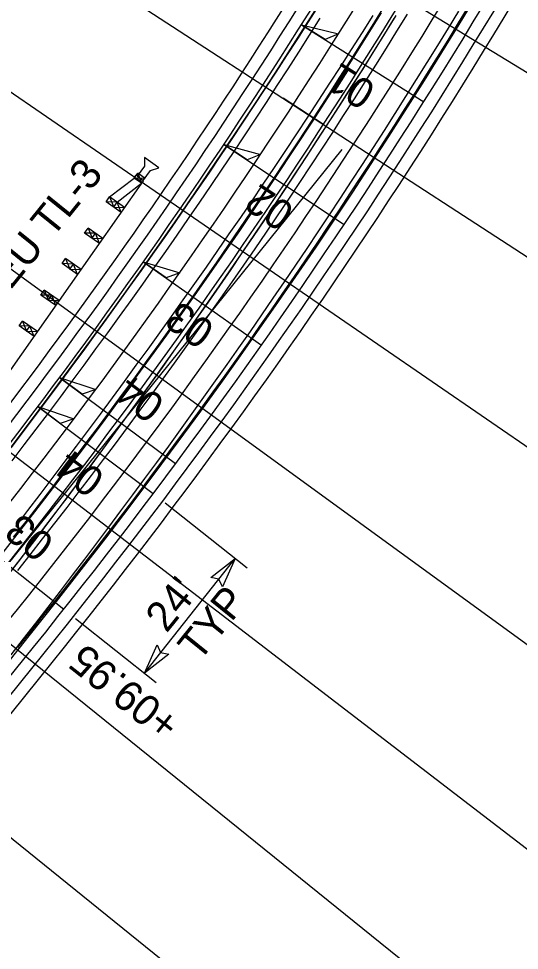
# Model space of a CAD drawing. Extents: x 2293233 to 2294507, y 892788 to 894229.
# Drawn here: x 2294077.1 to 2294160.2, y 893651.6 to 893806.4 of the extents above; entities that cross this region are included whole.
import ezdxf

# ---------------------------------------------------------------- set-up
doc = ezdxf.new("R2010")
doc.units = 0
for name, color, linetype in [('COGO Default Curve', 7, 'Continuous'), ('Prop Dimension', 7, 'Continuous'), ('Prop EOT', 7, 'Continuous'), ('Prop Guardrail Anchor Unit CELL', 7, 'Continuous'), ('Prop Horizontal Alignment', 7, 'Continuous'), ('Prop Paved Shoulder', 7, 'Continuous'), ('Prop Superelevation  Arrow CELL', 7, 'Continuous'), ('Prop Superelevation Label', 7, 'Continuous'), ('Scratch_Level_4', 7, 'Continuous'), ('Scratch_Level_5', 7, 'Continuous'), ('Typical Terminator CELL', 7, 'Continuous')]:
    doc.layers.add(name, color=color, linetype=linetype)

# ---------------------------------------------------------------- blocks, each defined once
blk = doc.blocks.new('TERMINATOR')
at = {"layer": 'Typical Terminator CELL'}
blk.add_lwpolyline([(-0.469, 0.081), (0, 0), (-0.471, -0.083), (-0.411, 0)], close=True, dxfattribs=at)

msp = doc.modelspace()

# ---------------------------------------------------------------- linework, layer by layer
at = {"layer": 'COGO Default Curve'}
for points in [[(2294153.14, 893810.31), (2294150.2, 893805.46), (2294144.41, 893796.11), (2294138.51, 893786.83), (2294132.51, 893777.61), (2294126.4, 893768.47), (2294120.19, 893759.4), (2294113.87, 893750.39), (2294110.57, 893745.78), (2294107.25, 893741.2), (2294103.51, 893736.09), (2294099.53, 893730.74), (2294095.52, 893725.42), (2294091.47, 893720.12), (2294087.39, 893714.85), (2294083.28, 893709.6), (2294078.73, 893703.85), (2294073.94, 893697.86), (2293868.79, 893443.63)], [(2294126.92, 893808.67), (2294125.15, 893805.87), (2294123.36, 893803.07), (2294121.56, 893800.29), (2294119.76, 893797.5), (2294117.95, 893794.73), (2294116.13, 893791.96), (2294114.29, 893789.19), (2294112.45, 893786.43), (2294110.61, 893783.68), (2294108.75, 893780.93), (2294106.88, 893778.19), (2294105, 893775.46), (2294103.12, 893772.73), (2294101.22, 893770.01), (2294099.32, 893767.3), (2294097.41, 893764.59), (2294095.49, 893761.89), (2294093.55, 893759.19), (2294091.61, 893756.5), (2294089.66, 893753.82), (2294087.71, 893751.14), (2294085.74, 893748.47), (2294083.77, 893745.8), (2294081.79, 893743.13), (2294079.8, 893740.47), (2294077.8, 893737.81), (2294075.8, 893735.16)], [(2293934.91, 893558.24), (2293982.19, 893616.89), (2294012.67, 893654.83), (2294024.95, 893670.19), (2294035.75, 893683.75), (2294045.26, 893695.77), (2294053.92, 893706.78), (2294061.7, 893716.77), (2294068.83, 893726.01), (2294075.49, 893734.76), (2294081.7, 893743.02), (2294085.47, 893748.1), (2294089.22, 893753.21), (2294092.74, 893758.07), (2294096.24, 893762.94), (2294099.7, 893767.84), (2294102.95, 893772.49), (2294106.35, 893777.42), (2294109.73, 893782.38), (2294113.08, 893787.36), (2294116.39, 893792.36), (2294119.68, 893797.38), (2294123.12, 893802.7), (2294126.34, 893807.75)], [(2294137.26, 893807.39), (2294131.61, 893798.35), (2294125.85, 893789.36), (2294119.8, 893780.17), (2294113.84, 893771.33), (2294107.78, 893762.55), (2294101.61, 893753.84), (2294095.16, 893744.94), (2294091.39, 893739.84), (2294087.6, 893734.78), (2294083.76, 893729.73), (2294079.69, 893724.45), (2294075.59, 893719.2), (2294071.04, 893713.45), (2294059.17, 893698.61), (2294044.74, 893680.7), (2293954.06, 893568.41)], [(2294075.83, 893700.72), (2294077.88, 893703.35), (2294079.92, 893705.99), (2294081.96, 893708.64), (2294083.99, 893711.29), (2294086.02, 893713.95), (2294088.04, 893716.61), (2294090.05, 893719.28), (2294092.06, 893721.95), (2294094.06, 893724.63), (2294096.05, 893727.31), (2294098.04, 893730), (2294100.01, 893732.69), (2294101.98, 893735.39), (2294103.94, 893738.1), (2294105.9, 893740.81), (2294107.84, 893743.52), (2294109.78, 893746.25), (2294111.71, 893748.98), (2294113.63, 893751.71), (2294115.55, 893754.45), (2294117.45, 893757.2), (2294119.35, 893759.95), (2294121.23, 893762.71), (2294123.11, 893765.48), (2294124.98, 893768.25), (2294126.84, 893771.02), (2294128.69, 893773.81), (2294130.54, 893776.6), (2294132.37, 893779.39), (2294134.19, 893782.19), (2294136.01, 893785), (2294137.81, 893787.81), (2294139.61, 893790.63), (2294141.4, 893793.46), (2294143.17, 893796.29), (2294144.94, 893799.13), (2294146.7, 893801.97), (2294148.45, 893804.82), (2294150.19, 893807.68)], [(2294137.48, 893808.02), (2294135.72, 893805.18), (2294133.94, 893802.34), (2294132.16, 893799.51), (2294130.37, 893796.68), (2294128.56, 893793.86), (2294126.75, 893791.05), (2294124.92, 893788.24), (2294123.09, 893785.44), (2294121.24, 893782.64), (2294119.39, 893779.85), (2294117.53, 893777.07), (2294115.65, 893774.3), (2294113.77, 893771.53), (2294111.88, 893768.77), (2294109.98, 893766.01), (2294108.06, 893763.26), (2294106.14, 893760.52), (2294104.21, 893757.79), (2294102.27, 893755.06), (2294100.32, 893752.34), (2294098.36, 893749.63), (2294096.39, 893746.92), (2294094.41, 893744.22), (2294092.42, 893741.52), (2294090.42, 893738.84), (2294088.41, 893736.16), (2294086.39, 893733.49), (2294084.36, 893730.82), (2294082.33, 893728.17), (2294080.28, 893725.52), (2294078.23, 893722.87), (2294076.16, 893720.24)], [(2294076.9, 893701.92), (2294079, 893704.52), (2294081.09, 893707.13), (2294083.16, 893709.74), (2294085.24, 893712.36), (2294087.3, 893714.99), (2294089.35, 893717.63), (2294091.4, 893720.27), (2294093.43, 893722.92), (2294095.46, 893725.58), (2294097.48, 893728.25), (2294099.48, 893730.93), (2294101.48, 893733.61), (2294103.47, 893736.3), (2294105.46, 893738.99), (2294107.43, 893741.7), (2294109.39, 893744.41), (2294111.34, 893747.12), (2294113.29, 893749.85), (2294115.22, 893752.58), (2294117.15, 893755.31), (2294119.06, 893758.06), (2294120.97, 893760.81), (2294122.86, 893763.57), (2294124.75, 893766.33), (2294126.63, 893769.1), (2294128.49, 893771.88), (2294130.35, 893774.66), (2294132.2, 893777.45), (2294134.04, 893780.25), (2294135.87, 893783.05), (2294137.69, 893785.86), (2294139.49, 893788.68), (2294141.29, 893791.5), (2294143.08, 893794.33), (2294144.86, 893797.17), (2294146.63, 893800.01), (2294148.39, 893802.85), (2294150.14, 893805.71), (2294151.88, 893808.57)], [(2294076.92, 893714.74), (2294078.98, 893717.35), (2294081.04, 893719.97), (2294083.08, 893722.59), (2294085.11, 893725.22), (2294087.13, 893727.86), (2294089.15, 893730.5), (2294091.15, 893733.15), (2294093.14, 893735.8), (2294095.13, 893738.46), (2294097.1, 893741.13), (2294099.07, 893743.81), (2294101.03, 893746.49), (2294102.97, 893749.18), (2294104.91, 893751.88), (2294106.84, 893754.58), (2294108.76, 893757.29), (2294110.67, 893760), (2294112.56, 893762.73), (2294114.45, 893765.45), (2294116.33, 893768.19), (2294118.21, 893770.93), (2294120.07, 893773.68), (2294121.92, 893776.44), (2294123.76, 893779.2), (2294125.59, 893781.96), (2294127.42, 893784.74), (2294129.23, 893787.52), (2294131.03, 893790.3), (2294132.83, 893793.1), (2294134.61, 893795.9), (2294136.38, 893798.7), (2294138.15, 893801.51), (2294139.9, 893804.33), (2294141.65, 893807.15)], [(2293932.89, 893536.61), (2294046.75, 893677.72), (2294053.42, 893686.04), (2294059.44, 893693.61), (2294065.01, 893700.68), (2294070.34, 893707.51), (2294075.44, 893714.1), (2294080.29, 893720.46), (2294085.11, 893726.85), (2294089.69, 893733), (2294096.97, 893742.96), (2294103.95, 893752.72), (2294107.4, 893757.63), (2294110.82, 893762.56), (2294114.21, 893767.5), (2294117.58, 893772.47), (2294120.92, 893777.46), (2294124.04, 893782.19), (2294127.32, 893787.21), (2294130.39, 893791.98), (2294133.61, 893797.04), (2294136.62, 893801.84), (2294139.78, 893806.94)], [(2294075.22, 893713.82), (2294077.24, 893716.46), (2294079.26, 893719.1), (2294081.26, 893721.74), (2294083.26, 893724.39), (2294085.26, 893727.04), (2294087.24, 893729.7), (2294089.22, 893732.37), (2294091.19, 893735.04), (2294093.15, 893737.71), (2294095.11, 893740.39), (2294097.06, 893743.08), (2294099, 893745.77), (2294100.93, 893748.46), (2294102.85, 893751.17), (2294104.77, 893753.87), (2294106.67, 893756.59), (2294108.57, 893759.31), (2294110.46, 893762.03), (2294112.34, 893764.76), (2294114.21, 893767.5), (2294116.07, 893770.24), (2294117.93, 893772.99), (2294119.77, 893775.75), (2294121.61, 893778.51), (2294123.44, 893781.27), (2294125.26, 893784.04), (2294127.06, 893786.82), (2294128.86, 893789.61), (2294130.65, 893792.39), (2294132.43, 893795.19), (2294134.21, 893797.99), (2294135.97, 893800.8), (2294137.72, 893803.61), (2294139.46, 893806.43)], [(2294127.1, 893806.48), (2294125.33, 893803.67), (2294123.55, 893800.87), (2294121.76, 893798.08), (2294119.96, 893795.29), (2294118.15, 893792.5), (2294116.33, 893789.72), (2294114.51, 893786.95), (2294112.67, 893784.19), (2294110.82, 893781.43), (2294108.96, 893778.68), (2294107.09, 893775.93), (2294105.22, 893773.2), (2294103.33, 893770.46), (2294101.43, 893767.74), (2294099.53, 893765.02), (2294097.61, 893762.31), (2294095.68, 893759.61), (2294093.75, 893756.91), (2294091.81, 893754.22), (2294089.85, 893751.53), (2294087.89, 893748.86), (2294085.92, 893746.19), (2294083.93, 893743.52), (2294081.94, 893740.87), (2294079.94, 893738.22), (2294077.93, 893735.58), (2294075.91, 893732.94)], [(2294135.89, 893806.96), (2294134.11, 893804.13), (2294132.32, 893801.3), (2294130.51, 893798.49), (2294128.7, 893795.68), (2294126.89, 893792.87), (2294125.06, 893790.07), (2294123.22, 893787.28), (2294121.37, 893784.49), (2294119.52, 893781.71), (2294117.65, 893778.93), (2294115.78, 893776.16), (2294113.9, 893773.4), (2294112, 893770.64), (2294110.1, 893767.89), (2294108.19, 893765.14), (2294106.27, 893762.41), (2294104.34, 893759.68), (2294102.4, 893756.95), (2294100.46, 893754.23), (2294098.5, 893751.52), (2294096.54, 893748.82), (2294094.56, 893746.12), (2294092.58, 893743.42), (2294090.59, 893740.73), (2294088.6, 893738.05), (2294086.6, 893735.38), (2294084.59, 893732.7), (2294082.58, 893730.04), (2294080.56, 893727.37), (2294078.54, 893724.71), (2294076.51, 893722.06)]]:
    msp.add_lwpolyline(points, dxfattribs=at)
for radius in [944, 956]:
    msp.add_arc((2293330.88, 894306.12), radius, 321.09608, 333.52096, dxfattribs=at)
at = {"layer": 'Prop Dimension'}
for p, q in [((2294101.39, 893725.96), (2294115, 893715.17)), ((2294097.94, 893697.68), (2294113.04, 893716.72)), ((2294086.53, 893706.73), (2294099.9, 893696.13))]:
    msp.add_line(p, q, dxfattribs=at)
at = {"layer": 'Prop EOT'}
msp.add_line((2293772.37, 893321.38), (2294079.51, 893701.97), dxfattribs=at)
for radius, end in [(938, 332.80359), (962, 333.52096), (962, 333.52096)]:
    msp.add_arc((2293330.88, 894306.12), radius, 321.09608, end, dxfattribs=at)
at = {"layer": 'Prop Guardrail Anchor Unit CELL'}
for p, q in [((2294097.96, 893783.37), (2294097.95, 893781.91)), ((2294100.33, 893781.63), (2294097.96, 893783.37)), ((2294097.95, 893781.91), (2294096.75, 893780.26)), ((2294097.74, 893779.54), (2294098.94, 893781.19)), ((2294098.94, 893781.19), (2294100.33, 893781.63)), ((2294070.91, 893741.21), (2294097.78, 893779.47)), ((2294092.17, 893776.81), (2294096.26, 893779.92)), ((2294096.26, 893779.92), (2294096.84, 893780.74)), ((2294096.26, 893779.92), (2294096.55, 893780.33)), ((2294097.49, 893779.06), (2294096.26, 893779.92)), ((2294098.07, 893779.88), (2294096.26, 893779.92)), ((2294096.75, 893780.26), (2294097.24, 893779.9)), ((2294098.07, 893779.88), (2294096.84, 893780.74)), ((2294096.84, 893780.74), (2294097.49, 893779.06)), ((2294097.24, 893779.9), (2294097.74, 893779.54)), ((2294093.42, 893775.93), (2294097.49, 893779.06)), ((2294091.59, 893775.99), (2294092.17, 893776.81)), ((2294094.67, 893775.05), (2294092.17, 893776.81)), ((2294092.17, 893776.81), (2294092.85, 893775.11)), ((2294094.1, 893774.23), (2294091.59, 893775.99)), ((2294093.42, 893775.93), (2294091.59, 893775.99)), ((2294092.85, 893775.11), (2294093.42, 893775.93)), ((2294092.85, 893775.11), (2294094.67, 893775.05)), ((2294094.1, 893774.23), (2294093.42, 893775.93)), ((2294088.02, 893770.8), (2294088.6, 893771.62)), ((2294091.05, 893769.89), (2294088.6, 893771.62)), ((2294088.6, 893771.62), (2294089.25, 893769.94)), ((2294090.48, 893769.07), (2294088.02, 893770.8)), ((2294089.82, 893770.75), (2294088.02, 893770.8)), ((2294089.25, 893769.94), (2294089.82, 893770.75)), ((2294089.25, 893769.94), (2294091.05, 893769.89)), ((2294090.48, 893769.07), (2294089.82, 893770.75)), ((2294084.29, 893765.72), (2294084.86, 893766.54)), ((2294086.86, 893763.92), (2294084.29, 893765.72)), ((2294086.15, 893765.64), (2294084.29, 893765.72)), ((2294087.43, 893764.74), (2294084.86, 893766.54)), ((2294084.86, 893766.54), (2294085.57, 893764.82)), ((2294085.57, 893764.82), (2294086.15, 893765.64)), ((2294086.86, 893763.92), (2294086.15, 893765.64)), ((2294085.57, 893764.82), (2294087.43, 893764.74)), ((2294080.75, 893760.5), (2294081.32, 893761.32)), ((2294083.81, 893759.58), (2294081.32, 893761.32)), ((2294081.32, 893761.32), (2294081.99, 893759.63)), ((2294083.23, 893758.76), (2294080.75, 893760.5)), ((2294082.57, 893760.45), (2294080.75, 893760.5)), ((2294081.99, 893759.63), (2294082.57, 893760.45)), ((2294081.99, 893759.63), (2294083.81, 893759.58)), ((2294083.23, 893758.76), (2294082.57, 893760.45)), ((2294083.23, 893758.76), (2294083.81, 893759.58)), ((2294077.12, 893755.36), (2294077.69, 893756.17)), ((2294080.19, 893754.42), (2294077.69, 893756.17)), ((2294077.69, 893756.17), (2294078.37, 893754.48)), ((2294079.61, 893753.6), (2294077.12, 893755.36)), ((2294078.94, 893755.3), (2294077.12, 893755.36)), ((2294078.37, 893754.48), (2294078.94, 893755.3)), ((2294078.37, 893754.48), (2294080.19, 893754.42)), ((2294079.61, 893753.6), (2294078.94, 893755.3))]:
    msp.add_line(p, q, dxfattribs=at)
at = {"layer": 'Prop Horizontal Alignment'}
msp.add_line((2294127.7, 893788.84), (2294120.99, 893793.2), dxfattribs=at)
msp.add_arc((2293330.88, 894306.12), 950, 321.09608, 333.52096, dxfattribs=at)
msp.add_arc((2293330.88, 894306.12), 950, 321.09608, 333.52096, dxfattribs=at)
at = {"layer": 'Prop Paved Shoulder'}
msp.add_line((2293773.93, 893320.13), (2294081.06, 893700.71), dxfattribs=at)
for radius, end in [(964, 333.52096), (936, 332.20827)]:
    msp.add_arc((2293330.88, 894306.12), radius, 321.09608, end, dxfattribs=at)
at = {"layer": 'Prop Superelevation  Arrow CELL'}
for p, q in [((2294124.06, 893805.41), (2294144.36, 893792.6)), ((2294111.16, 893785.53), (2294131.12, 893772.21)), ((2294097.76, 893765.99), (2294117.38, 893752.17)), ((2294083.87, 893746.79), (2294103.14, 893732.48)), ((2294080.25, 893741.95), (2294099.43, 893727.52)), ((2294065.76, 893723.2), (2294084.57, 893708.29))]:
    msp.add_line(p, q, dxfattribs=at)
for points in [[(2294124.06, 893805.41), (2294130.2, 893803.9), (2294127.97, 893802.94)], [(2294111.16, 893785.53), (2294117.26, 893783.87), (2294115.01, 893782.97)], [(2294097.76, 893765.99), (2294103.82, 893764.17), (2294101.54, 893763.33)], [(2294083.87, 893746.79), (2294089.88, 893744.82), (2294087.59, 893744.03)], [(2294080.25, 893741.95), (2294086.25, 893739.94), (2294083.95, 893739.17)]]:
    msp.add_lwpolyline(points, close=True, dxfattribs=at)
at = {"layer": 'Scratch_Level_4'}
for p, q in [((2294013.12, 893888.32), (2294268.96, 893731.65)), ((2294001.89, 893870.52), (2294253.52, 893707.16)), ((2293990.19, 893853.01), (2294237.44, 893683.09)), ((2293978.04, 893835.82), (2294220.73, 893659.46)), ((2293965.44, 893818.95), (2294203.4, 893636.27)), ((2293952.21, 893802.18), (2294185.67, 893613.78)), ((2293708.32, 893261.12), (2294130.82, 893784.65)), ((2293936.51, 893782.73), (2294169.97, 893594.32))]:
    msp.add_line(p, q, dxfattribs=at)
at = {"layer": 'Scratch_Level_5'}
msp.add_line((2294061.37, 893673.12), (2294082.62, 893699.45), dxfattribs=at)
for radius, end in [(966, 333.52096), (934, 331.58156)]:
    msp.add_arc((2293330.88, 894306.12), radius, 321.09608, end, dxfattribs=at)

# ---------------------------------------------------------------- block references
at = {"layer": 'Prop Dimension'}
for p, xscale, yscale, rotation in [((2294113.04, 893716.72), 10.60445387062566, 15.220700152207, 51.57832043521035), ((2294097.94, 893697.68), 10.604453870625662, 15.220700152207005, -128.42167956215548)]:
    msp.add_blockref('TERMINATOR', p, dxfattribs=dict(at, xscale=xscale, yscale=yscale, rotation=rotation))

# ---------------------------------------------------------------- texts
for s, rotation, p in [("24'", 51.0748, (2294101.63, 893704.22)), ('TYP', 51.0748, (2294107.05, 893699.41)), ('+09.95', 141.5783, (2294104.25, 893689.97))]:
    msp.add_text(s, height=5, rotation=rotation, dxfattribs=at).set_placement(p)
at = {"layer": 'Prop Guardrail Anchor Unit CELL'}
msp.add_text('GREU TL-3', height=5, rotation=51.0748, dxfattribs=at).set_placement((2294069.33, 893753.35))
at = {"layer": 'Prop Superelevation Label'}
for s, rotation, p in [('01', 147.7373, (2294136.69, 893795.28)), ('02', 146.2898, (2294123.17, 893775.04)), ('03', 144.8424, (2294109.92, 893755.39)), ('04', 143.0258, (2294101.63, 893742.96)), ('04', 143.0258, (2294091.66, 893730.6)), ('03', 141.5783, (2294083.27, 893719.82))]:
    msp.add_text(s, height=5, rotation=rotation, dxfattribs=at).set_placement(p)

doc.saveas('drawing.dxf')
